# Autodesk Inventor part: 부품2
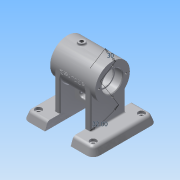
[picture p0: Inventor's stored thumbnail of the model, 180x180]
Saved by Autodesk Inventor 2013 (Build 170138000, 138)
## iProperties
Created: 2016-07
Part Number: 부품2
Material: 알루미늄 6061
Document SubType Name: Modeling
Designer: Administrator
Density: 2.71 g/cm^3
Mass: 498.133 g
Surface Area: 547.802 cm^2
Volume: 183.813 cm^3
Author: Administrator
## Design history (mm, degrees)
sketch "스케치1"
  geometry: L1 (0, 0)-(70, 0); L2 (0, 0)-(0, 27); L3 (0, 27)-(70, 27); L4 (70, 27)-(70, 16); L5 (70, 16)-(58.3, 16); L6 (58, 15.7)-(58, 14); L7 (58, 14)-(56, 14); L8 (56, 14)-(56, 19); L9 (53, 22)-(17, 22); L10 (14, 19)-(14, 14); L11 (14, 14)-(12, 14); L12 (12, 14)-(12, 15.7); L13 (11.7, 16)-(0, 16); A1 r 0.3 centre (11.7, 15.7) between (12, 15.7) and (11.7, 16); A2 r 0.3 centre (58.3, 15.7) between (58.3, 16) and (58, 15.7); A3 r 3 centre (17, 19) between (17, 22) and (14, 19); A4 r 3 centre (53, 19) between (56, 19) and (53, 22); 3 further points
  constraints: 26 end point, 8 point on circle, 8 tangent, 7 parallel, 7 point on line, 5 perpendicular, 4 centre point, 2 equal radius, 1 horizontal
  dimensions: "d0" = 70 distance of L1.start L1.end; "d1" = 54 diameter of L3 L1; "d2" = 32 diameter of L5 L1; "d3" = 32 diameter of L13 L1; "d5" = 28 diameter of L11 L1; "d7" = 28 diameter of L7 L1; "d8" = 44 diameter of L9 L1; "d10" = 70 distance between parallel lines of L2 L4; "d12" = 12 distance of point (12, 16) L13.end; "d13" = 42 distance of point (56, 22) point (14, 22); "d15" = 2 distance of L10.end L11.end; "d16" = 2 distance of L6.end L7.end; "d17" = 0.3 radius of A1; "d18" = 3 radius of A3
revolve "회전1" sketch "스케치1" stored, may be unused: angle "d19" = 90 deg
chamfer "모따기1" distance "d20" = 1; stored, may be unused: second distance "d21" = 2, angle "d22" = 45 deg
sketch "스케치2" dims "d23" = 42
  geometry: C1 r 27 at (0, 0) reference; C2 r 17 at (0, 0) reference; C3 r 2 at (0, 21); 1 further point
  constraints: 1 centre point, 1 coincident, 1 vertical alignment, 2 other
  dimensions: "d25" = 0 horizontal distance of C1.centre C3.centre; "d26" = 4 diameter of C3
hole "구멍1" sketch "스케치2" at (0, 21) diameter "d27" = 3.242; stored, may be unused: countersink angle "d31" = 90 deg, drill point angle "d33" = 118 deg; dims "d28" = 8, "d29" = 4, "d30" = 2, "d32" = 10
sketch "스케치3" dims "d37" = 42
  geometry: C1 r 27 at (0, 0) reference; C2 r 17 at (0, 0) reference; C3 r 2 at (0, 21); 1 further point
  constraints: 1 centre point, 1 coincident, 1 vertical alignment, 2 other
  dimensions: "d39" = 0 horizontal distance of C3.centre C1.centre; "d40" = 4 diameter of C3
hole "구멍2" sketch "스케치3" at (0, 21) diameter "d41" = 3.242; stored, may be unused: countersink angle "d45" = 90 deg, drill point angle "d47" = 118 deg; dims "d42" = 8, "d43" = 4, "d44" = 2, "d46" = 10
node "작업 평면2"
  node "작업 평면1"
sketch "스케치4"
  geometry: C1 r 5 at (22, 0); 1 further point
  constraints: 1 centre point
  dimensions: "d53" = 22 distance of point (0, 0) C1.centre; "d54" = 0 vertical distance of C1.centre point (0, 0); "d55" = 10 diameter of C1
extrude "돌출1" join sketch "스케치4" stored distance "d56" = 10; taper "d57" = 0 deg
sketch "스케치5"
  geometry: C1 r 5 at (0, 0) reference; C2 r 3 at (0, 0); 1 further point
  constraints: 1 centre point, 1 coincident
  dimensions: "d58" = 6 diameter of C2
hole "구멍3" sketch "스케치5" at (0, 0) diameter "d60" = 5.188; stored, may be unused: countersink angle "d64" = 90 deg, drill point angle "d66" = 118 deg; dims "d61" = 8, "d62" = 4, "d63" = 2, "d65" = 10
fillet "모깎기1" dims "d67" = 2
node "작업 평면6"
  node "작업 평면5"
sketch "스케치11"
  geometry: L1 (-27, 0)-(-27, -58); L2 (27, 0)-(27, -58); L3 (27, -58)-(-27, -58); A1 r 27 centre (0, 0) between (-27, 0) and (27, 0) reference; 1 further point
  constraints: 6 end point, 2 point on circle, 2 tangent, 1 parallel, 1 perpendicular, 1 vertical
  dimensions: "d83" = 58 distance from line of L3 point (0, 0)
extrude "돌출4" join sketch "스케치11" distance "d84" = 8; taper "d85" = 0 deg
sketch "스케치12"
  geometry: L1 (-27, 0)-(-27, -58) reference; L2 (-27, -58)-(27, -58) reference; L3 (27, -58)-(27, 0) reference; L4 (-27, -58)-(-45.629, -58); L5 (-50, -70)-(50, -70); L6 (45.632, -58)-(27, -58); L7 (-50, -70)-(-50, -58); L8 (-50, -58)-(-45.629, -58); L9 (50, -70)-(50, -58); L10 (50, -58)-(45.632, -58); A1 r 27 centre (0, 0) between (-27, 0) and (27, 0) reference; 1 further point
  constraints: 14 end point, 5 perpendicular, 1 collinear, 1 parallel
  dimensions: "d86" = 70 distance from line of point (0, 0) L5; "d89" = 100 distance of L5.start L5.end; "d90" = 50 horizontal distance of point (0, 0) L5.end
extrude "돌출5" join sketch "스케치12" distance "d91" = 35; taper "d92" = 0 deg
node "작업 평면7"
fillet "모깎기2" dims "d94" = 10
feature "면 기울기1" dims angle "d95" = 20 deg
fillet "모깎기3" dims "d96" = 5
node "작업 평면8"
fillet "모깎기4" dims "d97" = 10
feature "면 기울기2" dims angle "d98" = 20 deg
fillet "모깎기5" dims "d99" = 5
node "작업 평면9"
sketch "스케치15"
  geometry: L1 (0, 0)-(88.355, 0); L2 (0, 0)-(25.441, 15.898); 1 further point
  constraints: 4 end point, 1 coincident, 1 horizontal
  dimensions: "d115" = 32 deg angle of L1 L2; "d116" = 30 distance of L1.start L2.end
node "작업 평면10"
sketch "스케치16"
  geometry: C1 r 6 at (0, 0); 4 further points
  constraints: 1 centre point, 1 coincident
  dimensions: "d117" = 12 diameter of C1
extrude "돌출8" join sketch "스케치16" stored distance "d119" = 8; taper "d120" = 0 deg
sketch "스케치17"
  geometry: C1 r 6 at (0, 0) reference; C2 r 3 at (0, 0); 2 further points
  constraints: 2 coincident, 1 centre point
  dimensions: "d144" = 6 diameter of C2
sketch "스케치18"
  geometry: L1 (-27, -13)-(-27, 67) reference; L2 (8, 77)-(-17, 77) reference; L3 (83, -13)-(83, 67) reference; L4 (-27, 27)-(83, 27); L5 (8, 77)-(47.76, 77); L6 (75.131, -13)-(79.83, -13) reference; L7 (79.83, -13)-(79.83, 67) reference; L8 (75.131, 67)-(79.83, 67) reference; L9 (75.131, 67)-(75.131, -13) reference; L10 (83, -13)-(83, 67) reference; L11 (48, -23)-(73, -23) reference; L12 (48, -23)-(48, 77) reference; L13 (48, 77)-(73, 77) reference; C1 r 5 at (-14.5, 64.5); C2 r 5 at (-14.5, -10.5); C3 r 4.528 at (65.654, 65.553); A1 r 10 centre (73, 67) between (83, 67) and (73, 77) reference; A2 r 10 centre (73, -13) between (73, -23) and (83, -13) reference; 1 further point
  constraints: 4 end point, 3 centre point, 2 midpoint, 1 parallel
  dimensions: "d125" = 10 diameter of C1; "d132" = 75 distance of C1.centre C2.centre; "d133" = 37.5 distance from line of L4 C2.centre; "d135" = 10 diameter of C2; "d136" = 12.5 distance from line of L1 C2.centre; "d137" = 12.5 distance from line of L1 C1.centre
extrude "돌출9" cut sketch "스케치18" distance "d126" = 4; taper "d127" = 0 deg
sketch "스케치20"
  geometry: C1 r 5 at (0, 0) reference; C2 r 3 at (0, 0); 1 further point
  constraints: 1 centre point, 1 coincident
  dimensions: "d138" = 6 diameter of C2
extrude "돌출11" cut sketch "스케치20" stored distance "d140" = 4; taper "d141" = 0 deg
node "작업 평면11"
hole "구멍4" sketch "스케치17" diameter "d146" = 5.188; stored, may be unused: countersink angle "d150" = 82 deg, drill point angle "d152" = 118 deg; dims "d147" = 8, "d148" = 3.023, "d149" = 2, "d151" = 8
fillet "모깎기6" dims "d153" = 2
fillet "모깎기7" dims "d154" = 2
sketch "스케치21"
  geometry: L1 (0, -27)-(-70, -27) reference; L2 (-55, -10.583)-(-55, -58) reference; L3 (-15, -10.583)-(-15, -58) reference; L4 (-55, -27)-(-15, -27); L5 (-15, -27)-(-15, -48); L6 (-15, -48)-(-55, -48); L7 (-55, -48)-(-55, -27); 1 further point
  constraints: 8 end point, 3 point on line, 2 parallel, 1 horizontal, 1 perpendicular
  dimensions: "d155" = 21 distance between parallel lines of L4 L6
extrude "돌출12" join sketch "스케치21" stored distance "d157" = 8; taper "d158" = 0 deg
sketch "스케치22"
  geometry: L1 (55, 48)-(15, 48) reference; L2 (74.5, 70)-(80.5, 70) reference; L3 (-10.5, 70)-(-4.5, 70) reference; L4 (0, -27)-(70, -27) reference; L5 (35, -27)-(35, 48); L6 (43, 34.5)-(27, 34.5); L7 (43, 41.5)-(27, 41.5); A1 r 3.5 centre (43, 38) between (43, 34.5) and (43, 41.5); A2 r 3.5 centre (27, 38) between (27, 34.5) and (27, 41.5); 1 further point
  constraints: 6 end point, 4 point on circle, 4 tangent, 2 centre point, 2 midpoint
  dimensions: "d160" = 7 diameter of A1; "d162" = 7 diameter of A2; "d163" = 32 distance from line of L2 A1.centre; "d164" = 32 distance from line of L3 A2.centre; "d165" = 23 dimension on A2 A1; "d166" = 11.5 dimension on A1 L5
extrude "돌출13" cut sketch "스케치22" stored distance "d167" = 8; taper "d168" = 0 deg
fillet "모깎기8" dims "d169" = 2
fillet "모깎기9" dims "d170" = 2
node "작업 평면12"
sketch "스케치23"
  geometry: L1 (14.261, 3.002)-(55.739, 3.002); L2 (55.739, 3.002)-(55.739, -3.002); L3 (55.739, -3.002)-(14.261, -3.002); L4 (14.261, -3.002)-(14.261, 3.002); L5 (14.261, 0)-(55.739, 0); L6 (35, 3.002)-(35, -3.002); 1 further point
  constraints: 4 end point, 4 midpoint, 2 other
  dimensions: "d172" = 35 distance from line of point (0, 0) L6; "d173" = 0 distance from line of point (0, 0) L5
feature "엠보싱1" sketch "스케치23" dims "d0" = 70, "d1" = 54, "d2" = 32, "d3" = 32, "d5" = 28, "d7" = 28, "d8" = 44, "d10" = 70, "d12" = 12, "d13" = 42, "d15" = 2, "d16" = 2, "d17" = 0.3, "d18" = 3, "d174" = 0.5, "d175" = 0
node "솔리드1"
pattern_circular "원형 패턴1" dims angle "d35" = 360 deg
pattern_circular "원형 패턴2" dims angle "d49" = 360 deg
mirror "대칭1"
mirror "대칭2"
mirror "대칭3"
node "투영된 루프1"
node "투영된 루프2"
other parameters: "d171" = -34.25
